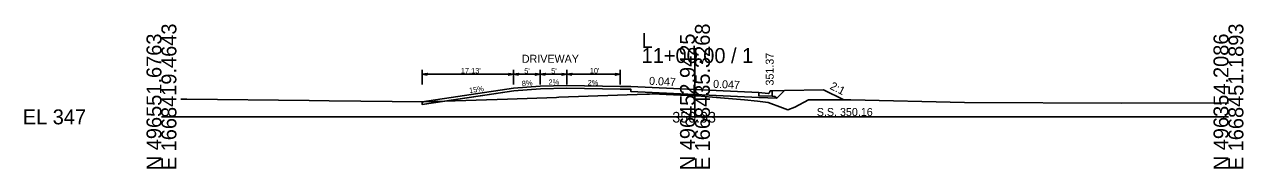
# Model space of a CAD drawing. Extents: x -26 to 203, y -10 to 5517.
# Drawn here: x -25.7 to 202.8, y 990.3 to 1017.3 of the extents above; entities that cross this region are included whole.
import ezdxf

# ---------------------------------------------------------------- set-up
doc = ezdxf.new("R2010")
doc.units = 0
for name, color, linetype in [('Exist Cross Section Cell', 7, 'Continuous'), ('Exist XS Center Line Elevation Label', 7, 'Continuous'), ('Exist XS Ground Line', 7, 'Continuous'), ('Prop XS Earthwork Shape', 7, 'Continuous'), ('Prop XS Finish Grade', 7, 'Continuous'), ('Prop XS Finish Grade Concrete', 7, 'Continuous'), ('Prop XS Finish Grade CurbGutter', 7, 'Continuous'), ('Prop XS Finish Grade Earthwork', 7, 'Continuous'), ('Prop XS Finish Grade Pavement', 7, 'Continuous'), ('Prop XS Geopak Shape', 7, 'Continuous'), ('Prop XS Hydro Elevations', 7, 'Continuous'), ('Prop XS Pvmt Edge Slope', 7, 'Continuous'), ('Prop XS SE Text', 7, 'Continuous'), ('Prop XS Side Slope Text', 7, 'Continuous'), ('Prop XS SS Elevation Text', 7, 'Continuous'), ('Prop XS Subgrade CurbGutter', 7, 'Continuous'), ('Prop XS Subgrade Earthwork', 7, 'Continuous'), ('Prop XSC Text', 7, 'Continuous'), ('Typical Terminator CELL', 7, 'Continuous')]:
    doc.layers.add(name, color=color, linetype=linetype)

msp = doc.modelspace()

# ---------------------------------------------------------------- linework, layer by layer
at = {"layer": 'Exist Cross Section Cell'}
for p, q in [((100, 1000), (100, 1012.89)), ((0, 1000), (100, 1000)), ((100, 1000), (200, 1000))]:
    msp.add_line(p, q, dxfattribs=at)
at = {"layer": 'Exist XS Ground Line'}
for p, q in [((3.63, 1003.32), (4.78, 1003.3)), ((4.78, 1003.3), (27.71, 1003.04)), ((49.15, 1002.79), (64.87, 1003.32)), ((64.87, 1003.32), (74.07, 1003.64)), ((74.07, 1003.64), (74.47, 1003.66)), ((74.47, 1003.66), (90.98, 1004.23)), ((90.98, 1004.23), (91.46, 1004.26)), ((91.46, 1004.26), (92.12, 1004.3)), ((92.12, 1004.3), (94.58, 1004.2)), ((94.58, 1004.2), (100, 1003.93)), ((100, 1003.93), (100.43, 1003.91)), ((100.43, 1003.91), (103.27, 1003.71)), ((103.27, 1003.71), (109.29, 1003.22)), ((27.71, 1003.04), (31.41, 1002.99)), ((31.41, 1002.99), (49.15, 1002.79)), ((109.29, 1003.22), (111.73, 1002.94)), ((111.73, 1002.94), (113.73, 1002.7)), ((113.73, 1002.7), (116.39, 1001.68)), ((116.39, 1001.68), (117.41, 1001.31)), ((117.41, 1001.31), (118.7, 1001.79)), ((118.7, 1001.79), (121.31, 1003.16)), ((121.31, 1003.16), (129.19, 1003.16)), ((129.19, 1003.16), (150.52, 1002.66)), ((150.52, 1002.66), (179.98, 1002.55)), ((179.98, 1002.55), (199.05, 1002.6)), ((199.05, 1002.6), (200, 1002.58))]:
    msp.add_line(p, q, dxfattribs=at)
at = {"layer": 'Prop XS Earthwork Shape'}
for points in [[(112, 1003.63), (100, 1004.19), (88, 1004.75), (88, 1005.17), (85.99, 1005.17), (76.01, 1005.37), (71.02, 1005.27), (66.06, 1004.87), (53.11, 1002.93), (64.87, 1003.32), (74.07, 1003.64), (74.47, 1003.66), (90.98, 1004.23), (91.46, 1004.26), (92.12, 1004.3), (94.58, 1004.2), (100, 1003.93), (100.43, 1003.91), (103.27, 1003.71), (109.29, 1003.22), (111.73, 1002.94), (113.73, 1002.7), (116.39, 1001.68), (117.41, 1001.31), (118.7, 1001.79), (121.31, 1003.16), (127.92, 1003.16), (124.09, 1005.08), (116.78, 1004.92), (115.33, 1003.48)], [(48.87, 1002.8), (49.15, 1002.79), (53.11, 1002.93), (48.87, 1002.29)]]:
    msp.add_lwpolyline(points, close=True, dxfattribs=at)
at = {"layer": 'Prop XS Finish Grade'}
msp.add_line((114.5, 1004.87), (116.78, 1004.92), dxfattribs=at)
at = {"layer": 'Prop XS Finish Grade Concrete'}
for p, q in [((71, 1005.77), (66, 1005.37)), ((76, 1005.87), (71, 1005.77)), ((86, 1005.67), (76, 1005.87)), ((88, 1005.67), (86, 1005.67)), ((66, 1005.37), (48.87, 1002.8))]:
    msp.add_line(p, q, dxfattribs=at)
at = {"layer": 'Prop XS Finish Grade CurbGutter'}
for p, q in [((112, 1004.55), (113.75, 1004.4)), ((113.75, 1004.4), (113.87, 1004.42)), ((113.87, 1004.42), (113.97, 1004.51)), ((113.97, 1004.51), (114.03, 1004.76)), ((114.03, 1004.76), (114.12, 1004.85)), ((114.25, 1004.87), (114.12, 1004.85)), ((114.5, 1004.87), (114.25, 1004.87))]:
    msp.add_line(p, q, dxfattribs=at)
at = {"layer": 'Prop XS Finish Grade Earthwork'}
for p, q in [((116.78, 1004.92), (124.09, 1005.08)), ((124.09, 1005.08), (127.92, 1003.16))]:
    msp.add_line(p, q, dxfattribs=at)
at = {"layer": 'Prop XS Finish Grade Pavement'}
for p, q in [((88, 1005.67), (100, 1005.11)), ((100, 1005.11), (112, 1004.55))]:
    msp.add_line(p, q, dxfattribs=at)
at = {"layer": 'Prop XS Geopak Shape'}
msp.add_lwpolyline([(100, 1005.11), (112, 1004.55), (113.75, 1004.4), (113.87, 1004.42), (113.97, 1004.51), (114.03, 1004.76), (114.12, 1004.85), (114.25, 1004.87), (114.5, 1004.87), (116.78, 1004.92), (124.09, 1005.08), (127.92, 1003.16), (121.31, 1003.16), (118.7, 1001.79), (117.41, 1001.31), (116.39, 1001.68), (113.73, 1002.7), (111.73, 1002.94), (109.29, 1003.22), (103.27, 1003.71), (100.43, 1003.91), (100, 1003.93), (94.58, 1004.2), (92.12, 1004.3), (91.46, 1004.26), (90.98, 1004.23), (74.47, 1003.66), (74.07, 1003.64), (64.87, 1003.32), (49.15, 1002.79), (48.87, 1002.8), (66, 1005.37), (71, 1005.77), (76, 1005.87), (86, 1005.67), (88, 1005.67)], close=True, dxfattribs=at)
at = {"layer": 'Prop XS Pvmt Edge Slope'}
for p, q in [((114.5, 1003.85), (115, 1003.83)), ((115, 1003.83), (115.33, 1003.48))]:
    msp.add_line(p, q, dxfattribs=at)
at = {"layer": 'Prop XS Subgrade CurbGutter'}
for p, q in [((112, 1004.55), (112, 1003.97)), ((112, 1003.97), (114.5, 1003.85)), ((114.5, 1003.85), (114.5, 1004.87))]:
    msp.add_line(p, q, dxfattribs=at)
at = {"layer": 'Prop XS Subgrade Earthwork'}
for p, q in [((66.06, 1004.87), (48.87, 1002.29)), ((71.02, 1005.27), (66.06, 1004.87)), ((76.01, 1005.37), (71.02, 1005.27)), ((85.99, 1005.17), (75.99, 1005.37)), ((88, 1005.17), (86, 1005.17)), ((88, 1005.17), (88, 1004.75)), ((88, 1004.75), (88, 1004.75)), ((100, 1004.19), (88, 1004.75)), ((112, 1003.63), (100, 1004.19)), ((112, 1003.63), (112, 1003.63)), ((112, 1003.63), (115.33, 1003.48)), ((115.33, 1003.48), (116.78, 1004.92)), ((48.87, 1002.8), (48.87, 1002.29))]:
    msp.add_line(p, q, dxfattribs=at)
at = {"layer": 'Prop XSC Text'}
for p, q in [((48.87, 1006.07), (48.87, 1008.79)), ((66, 1007.97), (48.87, 1007.97)), ((66, 1006.07), (66, 1008.79)), ((71, 1007.97), (66, 1007.97)), ((71, 1006.07), (71, 1008.79)), ((76, 1007.97), (71, 1007.97)), ((76, 1006.07), (76, 1008.79)), ((86, 1007.97), (76, 1007.97)), ((86, 1006.07), (86, 1008.79))]:
    msp.add_line(p, q, dxfattribs=at)
at = {"layer": 'Typical Terminator CELL'}
for points in [[(49.81, 1007.81), (48.87, 1007.97), (49.81, 1008.14), (49.69, 1007.97)], [(65.06, 1008.13), (66, 1007.97), (65.06, 1007.8), (65.18, 1007.97)], [(66.94, 1007.81), (66, 1007.97), (66.94, 1008.14), (66.82, 1007.97)], [(70.06, 1008.13), (71, 1007.97), (70.06, 1007.8), (70.18, 1007.97)], [(71.94, 1007.81), (71, 1007.97), (71.94, 1008.14), (71.82, 1007.97)], [(75.06, 1008.13), (76, 1007.97), (75.06, 1007.8), (75.18, 1007.97)], [(76.94, 1007.81), (76, 1007.97), (76.94, 1008.14), (76.82, 1007.97)], [(85.06, 1008.13), (86, 1007.97), (85.06, 1007.8), (85.18, 1007.97)]]:
    msp.add_lwpolyline(points, close=True, dxfattribs=at)

# ---------------------------------------------------------------- texts
at = {"layer": 'Exist Cross Section Cell'}
for s, p in [('E 1668419.4643', (2.8, 990)), ('E 1668435.3268', (102.8, 990)), ('E 1668451.1893', (202.8, 990)), ('N 496551.6763', (0, 990)), ('N 496452.9425', (100, 990)), ('N 496354.2086', (200, 990))]:
    msp.add_text(s, height=2.8, rotation=90, dxfattribs=at).set_placement(p)
for s, p in [('L', (90, 1012.89)), ('11+00.00 / 1', (90, 1010.09)), ('EL 347', (-26, 998.6))]:
    msp.add_text(s, height=2.8, dxfattribs=at).set_placement(p)
at = {"layer": 'Exist XS Center Line Elevation Label'}
msp.add_text('350.93', height=2, dxfattribs=at).set_placement((95.75, 998.93))
at = {"layer": 'Prop XS Hydro Elevations'}
msp.add_text('351.37', height=1.5, rotation=90, dxfattribs=at).set_placement((114.75, 1005.87))
at = {"layer": 'Prop XS SE Text'}
for p in [(91.37, 1006.01), (103.37, 1005.45)]:
    msp.add_text('0.047', height=1.5, rotation=357.3281, dxfattribs=at).set_placement(p)
at = {"layer": 'Prop XS Side Slope Text'}
msp.add_text('2:1', height=1.5, rotation=333.4349, dxfattribs=at).set_placement((125.18, 1005.3))
at = {"layer": 'Prop XS SS Elevation Text'}
msp.add_text('S.S. 350.16', height=1.5, dxfattribs=at).set_placement((122.84, 1000.16))
at = {"layer": 'Prop XSC Text'}
for s, height, p in [('DRIVEWAY', 1.5, (67.55, 1010.13)), ("17.13'", 1, (56.12, 1008.14)), ("5'", 1, (68.01, 1008.1)), ("5'", 1, (73.05, 1008.1)), ("10'", 1, (80.29, 1008.14))]:
    msp.add_text(s, height=height, dxfattribs=at).set_placement(p)
for s, rotation, p in [('15%', 8.5308, (57.74, 1004.43)), ('8%', 4.5739, (67.59, 1005.74)), ('2%', 1.1458, (72.56, 1006)), ('2%', 358.8542, (79.88, 1005.91))]:
    msp.add_text(s, height=1, rotation=rotation, dxfattribs=at).set_placement(p)

doc.saveas('drawing.dxf')
